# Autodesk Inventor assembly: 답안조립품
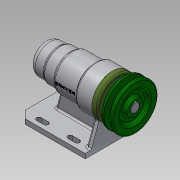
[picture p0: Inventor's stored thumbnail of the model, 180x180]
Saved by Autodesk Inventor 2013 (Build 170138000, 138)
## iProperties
Created: 2017-09
Part Number: 답안조립품
Document SubType Name: Assembly
Designer: Administrator
Author: Administrator
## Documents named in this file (12)
- C:\Documents and Settings\Administrator\바탕 화면\470908V1002\답안조립품.iam
- C:\Documents and Settings\Administrator\바탕 화면\470908V1002\1.본체.ipt
- C:\Documents and Settings\Administrator\바탕 화면\470908V1002\베어링 6004.ipt
- C:\Documents and Settings\Administrator\바탕 화면\470908V1002\베어링 51202.ipt
- C:\Documents and Settings\Administrator\바탕 화면\470908V1002\어댑터슬리브.ipt
- C:\Documents and Settings\Administrator\바탕 화면\470908V1002\축.ipt
- C:\Documents and Settings\Administrator\바탕 화면\470908V1002\볼트 M4 x 12.ipt
- C:\Documents and Settings\Administrator\바탕 화면\470908V1002\커버.ipt
- C:\Documents and Settings\Administrator\바탕 화면\470908V1002\오일 실 20x35x7.ipt
- C:\Documents and Settings\Administrator\바탕 화면\470908V1002\키 5 x 5 x 16.ipt
- C:\Documents and Settings\Administrator\바탕 화면\470908V1002\V벨트풀리.ipt
- C:\Documents and Settings\Administrator\바탕 화면\470908V1002\멈춤나사 M3x8.ipt
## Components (2 placed, 2 different names)
1. 1.본체:1
2. V벨트풀리:1 — 각도:1
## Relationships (1: Angle 1)
- 각도:1 [Angle]: V벨트풀리:1
